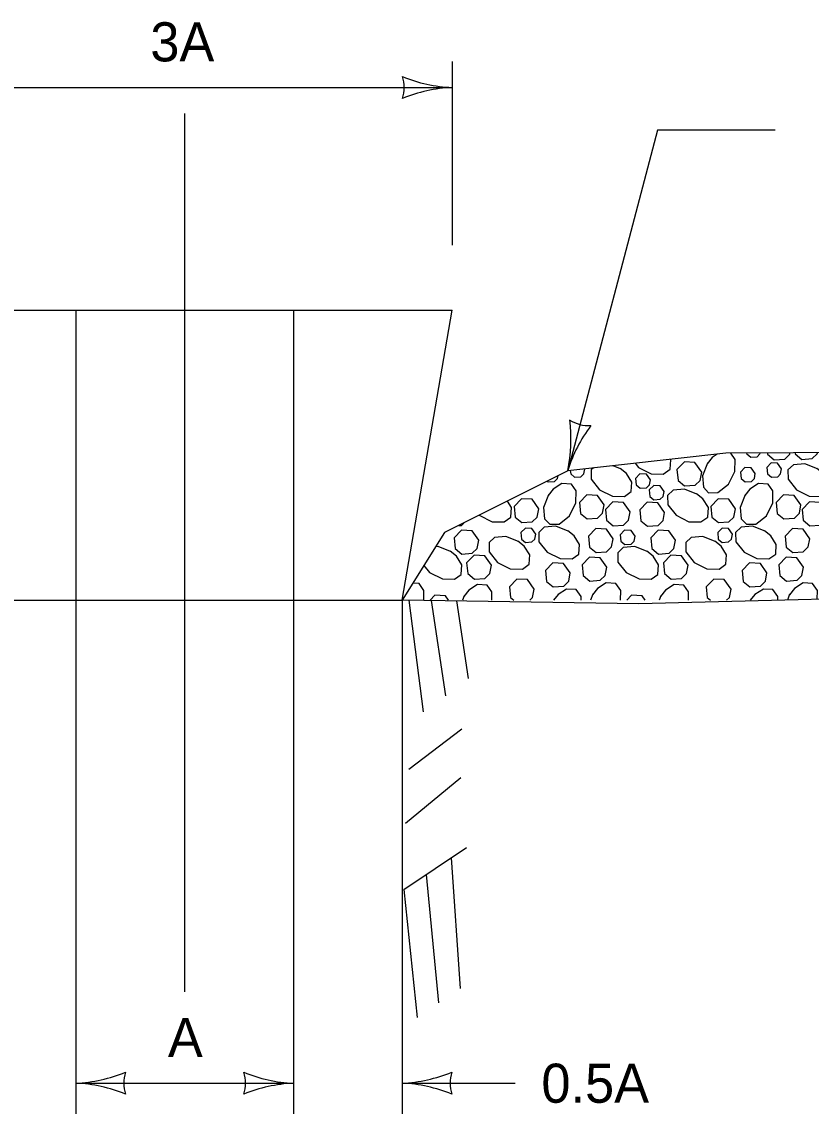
# Model space of a CAD drawing. Extents: x 49991.4 to 50021, y 49987.6 to 50011.4.
# Drawn here: x 50009.772 to 50010.982, y 49996.429 to 49998.093 of the extents above; entities that cross this region are included whole.
import ezdxf

# ---------------------------------------------------------------- set-up
doc = ezdxf.new("R2010")
doc.units = 0
for name, color, linetype in [('Level 1', 7, 'Continuous'), ('Level 2', 7, 'Continuous'), ('Level 3', 7, 'Continuous'), ('Level 6', 7, 'Continuous')]:
    doc.layers.add(name, color=color, linetype=linetype)

msp = doc.modelspace()

# ---------------------------------------------------------------- linework, layer by layer
at = {"layer": 'Level 1'}
for p, q in [((50009.6034, 49997.6503), (50010.4318, 49997.6503)), ((50009.6425, 49997.6503), (50010.4321, 49997.6503)), ((50009.8552, 49997.6503), (50009.8552, 49994.0392)), ((50010.1886, 49997.6503), (50010.1886, 49994.0392)), ((50010.3553, 49997.2058), (50010.4321, 49997.6503)), ((50010.6354, 49997.407), (50010.6353, 49997.4071)), ((50010.6901, 49997.4073), (50010.6785, 49997.4119)), ((50009.6885, 49997.2058), (50010.3553, 49997.2058)), ((50010.3553, 49997.2058), (50010.3553, 49994.0392)), ((50010.3653, 49997.2057), (50010.3872, 49997.0343)), ((50010.3996, 49997.2051), (50010.4218, 49997.0592)), ((50010.4385, 49997.2045), (50010.4566, 49997.0856)), ((50010.4503, 49997.2123), (50010.4477, 49997.2058)), ((50010.6477, 49997.2148), (50010.6441, 49997.2058)), ((50010.7518, 49997.2123), (50010.7492, 49997.2058)), ((50010.9492, 49997.2148), (50010.9457, 49997.2059)), ((50010.3655, 49996.9466), (50010.4466, 49997.0086)), ((50010.3603, 49996.8636), (50010.445, 49996.9338)), ((50010.3577, 49996.762), (50010.4541, 49996.8266)), ((50010.4305, 49996.8108), (50010.4444, 49996.6101)), ((50010.3918, 49996.7849), (50010.4107, 49996.588)), ((50010.3577, 49996.762), (50010.3781, 49996.5657))]:
    msp.add_line(p, q, dxfattribs=at)
for points in [[(50011.482, 49997.443), (50011.1627, 49997.4327), (50010.8516, 49997.431), (50010.609, 49997.4042), (50010.4204, 49997.3093), (50010.3553, 49997.2058)], [(50010.7123, 49997.4156), (50010.7174, 49997.4092), (50010.737, 49997.3993), (50010.7555, 49997.399), (50010.7659, 49997.4064), (50010.7669, 49997.4212), (50010.7666, 49997.4216)], [(50010.8144, 49997.4022), (50010.8041, 49997.4167), (50010.7878, 49997.4177), (50010.7764, 49997.4059), (50010.7781, 49997.3894), (50010.7882, 49997.381), (50010.8043, 49997.3821), (50010.8119, 49997.3895), (50010.8144, 49997.4022)], [(50010.8231, 49997.4157), (50010.8155, 49997.3965), (50010.817, 49997.3789), (50010.825, 49997.3705), (50010.8393, 49997.3708), (50010.8555, 49997.3835), (50010.8653, 49997.4031), (50010.8656, 49997.4216), (50010.8589, 49997.4311)], [(50010.8381, 49997.4295), (50010.8303, 49997.4246), (50010.8226, 49997.4149)], [(50010.8833, 49997.4312), (50010.8834, 49997.4301), (50010.8895, 49997.425), (50010.8992, 49997.4258), (50010.9037, 49997.4302), (50010.9039, 49997.4313)], [(50010.9153, 49997.4314), (50010.9155, 49997.4295), (50010.9256, 49997.4211), (50010.9417, 49997.4222), (50010.9493, 49997.4296), (50010.9497, 49997.4315)], [(50010.9575, 49997.4316), (50010.9576, 49997.4301), (50010.9677, 49997.4217), (50010.9839, 49997.4229), (50010.9915, 49997.4302), (50010.9918, 49997.4318)], [(50010.613, 49997.4047), (50010.6136, 49997.3993), (50010.6196, 49997.3943), (50010.6293, 49997.395), (50010.6339, 49997.3994), (50010.6354, 49997.407)], [(50010.6483, 49997.4086), (50010.645, 49997.4054), (50010.6452, 49997.3912), (50010.6579, 49997.3749), (50010.6776, 49997.3651), (50010.696, 49997.3648), (50010.7065, 49997.3722), (50010.7074, 49997.3869), (50010.699, 49997.4001), (50010.6893, 49997.4078)], [(50010.8966, 49997.3998), (50010.8904, 49997.4086), (50010.8806, 49997.4091), (50010.8738, 49997.402), (50010.8748, 49997.3921), (50010.8808, 49997.3871), (50010.8905, 49997.3878), (50010.8951, 49997.3922), (50010.8966, 49997.3998)], [(50010.9369, 49997.407), (50010.9308, 49997.4158), (50010.921, 49997.4163), (50010.9141, 49997.4093), (50010.9151, 49997.3993), (50010.9212, 49997.3943), (50010.9309, 49997.395), (50010.9354, 49997.3994), (50010.9369, 49997.407)], [(50010.9917, 49997.4073), (50010.9725, 49997.4149), (50010.9549, 49997.4134), (50010.9465, 49997.4054), (50010.9468, 49997.3912), (50010.9595, 49997.3749), (50010.9791, 49997.3651), (50010.9976, 49997.3648), (50011.008, 49997.3722), (50011.009, 49997.3869), (50011.0006, 49997.4001), (50010.9909, 49997.4078)], [(50010.5795, 49997.3673), (50010.5719, 49997.3481), (50010.5734, 49997.3305), (50010.5814, 49997.3222), (50010.5957, 49997.3224), (50010.6119, 49997.3351), (50010.6217, 49997.3548), (50010.6221, 49997.3733), (50010.6147, 49997.3837), (50010.5999, 49997.3847), (50010.5867, 49997.3762), (50010.579, 49997.3665)], [(50010.5776, 49997.3884), (50010.5793, 49997.3871), (50010.589, 49997.3878), (50010.5935, 49997.3922), (50010.5944, 49997.3969)], [(50010.7358, 49997.3902), (50010.7296, 49997.399), (50010.7198, 49997.3995), (50010.713, 49997.3924), (50010.714, 49997.3825), (50010.72, 49997.3775), (50010.7297, 49997.3782), (50010.7343, 49997.3826), (50010.7358, 49997.3902)], [(50010.8811, 49997.3673), (50010.8735, 49997.3481), (50010.875, 49997.3305), (50010.8829, 49997.3222), (50010.8972, 49997.3224), (50010.9135, 49997.3351), (50010.9233, 49997.3548), (50010.9236, 49997.3733), (50010.9162, 49997.3837), (50010.9015, 49997.3847), (50010.8883, 49997.3762), (50010.8806, 49997.3665)], [(50010.7569, 49997.3724), (50010.7508, 49997.3812), (50010.7409, 49997.3817), (50010.7341, 49997.3747), (50010.7351, 49997.3648), (50010.7412, 49997.3597), (50010.7509, 49997.3604), (50010.7554, 49997.3648), (50010.7569, 49997.3724)], [(50010.8072, 49997.3683), (50010.7881, 49997.3759), (50010.7705, 49997.3744), (50010.7621, 49997.3664), (50010.7624, 49997.3521), (50010.7751, 49997.3359), (50010.7947, 49997.3261), (50010.8132, 49997.3257), (50010.8236, 49997.3331), (50010.8246, 49997.3479), (50010.8161, 49997.361), (50010.8065, 49997.3688)], [(50010.4734, 49997.336), (50010.4735, 49997.3359), (50010.4931, 49997.3261), (50010.5116, 49997.3257), (50010.522, 49997.3331), (50010.523, 49997.3479), (50010.5167, 49997.3577)], [(50010.5648, 49997.3458), (50010.5545, 49997.3604), (50010.5382, 49997.3613), (50010.5268, 49997.3495), (50010.5284, 49997.333), (50010.5385, 49997.3246), (50010.5547, 49997.3258), (50010.5623, 49997.3331), (50010.5647, 49997.3458)], [(50010.665, 49997.3517), (50010.6548, 49997.3663), (50010.6384, 49997.3672), (50010.627, 49997.3554), (50010.6287, 49997.3389), (50010.6388, 49997.3305), (50010.6549, 49997.3317), (50010.6625, 49997.339), (50010.665, 49997.3517)], [(50010.7047, 49997.341), (50010.6945, 49997.3556), (50010.6781, 49997.3565), (50010.6668, 49997.3447), (50010.6684, 49997.3282), (50010.6785, 49997.3198), (50010.6947, 49997.321), (50010.7023, 49997.3283), (50010.7047, 49997.341)], [(50010.7576, 49997.3404), (50010.7473, 49997.355), (50010.731, 49997.3559), (50010.7196, 49997.3441), (50010.7213, 49997.3276), (50010.7314, 49997.3192), (50010.7475, 49997.3204), (50010.7551, 49997.3277), (50010.7576, 49997.3404)], [(50010.8663, 49997.3458), (50010.8561, 49997.3604), (50010.8397, 49997.3613), (50010.8283, 49997.3495), (50010.83, 49997.333), (50010.8401, 49997.3246), (50010.8562, 49997.3258), (50010.8638, 49997.3331), (50010.8663, 49997.3458)], [(50010.9665, 49997.3517), (50010.9563, 49997.3663), (50010.9399, 49997.3672), (50010.9286, 49997.3554), (50010.9302, 49997.3389), (50010.9403, 49997.3305), (50010.9565, 49997.3317), (50010.9641, 49997.339), (50010.9665, 49997.3517)], [(50011.0063, 49997.341), (50010.996, 49997.3556), (50010.9797, 49997.3565), (50010.9683, 49997.3447), (50010.97, 49997.3282), (50010.9801, 49997.3198), (50010.9962, 49997.321), (50011.0038, 49997.3283), (50011.0063, 49997.341)], [(50010.4419, 49997.3201), (50010.446, 49997.3204), (50010.4497, 49997.324)], [(50010.6099, 49997.3116), (50010.5907, 49997.3192), (50010.5731, 49997.3177), (50010.5648, 49997.3097), (50010.565, 49997.2954), (50010.5777, 49997.2792), (50010.5974, 49997.2694), (50010.6159, 49997.2691), (50010.6263, 49997.2765), (50010.6273, 49997.2912), (50010.6188, 49997.3044), (50010.6091, 49997.3121)], [(50010.9115, 49997.3116), (50010.8923, 49997.3192), (50010.8747, 49997.3177), (50010.8663, 49997.3097), (50010.8666, 49997.2954), (50010.8793, 49997.2792), (50010.8989, 49997.2694), (50010.9174, 49997.2691), (50010.9278, 49997.2765), (50010.9288, 49997.2912), (50010.9204, 49997.3044), (50010.9107, 49997.3121)], [(50010.4728, 49997.2977), (50010.4626, 49997.3123), (50010.4462, 49997.3132), (50010.4349, 49997.3014), (50010.4365, 49997.2849), (50010.4466, 49997.2765), (50010.4628, 49997.2777), (50010.4704, 49997.2851), (50010.4728, 49997.2977)], [(50010.5335, 49997.2959), (50010.5144, 49997.3035), (50010.4968, 49997.3019), (50010.4884, 49997.294), (50010.4887, 49997.2797), (50010.5014, 49997.2635), (50010.521, 49997.2536), (50010.5395, 49997.2533), (50010.5499, 49997.2607), (50010.5509, 49997.2755), (50010.5424, 49997.2886), (50010.5328, 49997.2964)], [(50010.5601, 49997.3071), (50010.5539, 49997.3158), (50010.5441, 49997.3164), (50010.5373, 49997.3093), (50010.5383, 49997.2994), (50010.5444, 49997.2944), (50010.554, 49997.2951), (50010.5586, 49997.2995), (50010.5601, 49997.3071)], [(50010.6786, 49997.2999), (50010.6684, 49997.3145), (50010.652, 49997.3155), (50010.6407, 49997.3037), (50010.6423, 49997.2871), (50010.6524, 49997.2787), (50010.6686, 49997.2799), (50010.6762, 49997.2873), (50010.6786, 49997.2999)], [(50010.7122, 49997.3037), (50010.7061, 49997.3125), (50010.6963, 49997.313), (50010.6894, 49997.3059), (50010.6904, 49997.296), (50010.6965, 49997.291), (50010.7062, 49997.2917), (50010.7107, 49997.2961), (50010.7122, 49997.3037)], [(50010.7744, 49997.2977), (50010.7641, 49997.3123), (50010.7478, 49997.3132), (50010.7364, 49997.3014), (50010.7381, 49997.2849), (50010.7482, 49997.2765), (50010.7643, 49997.2777), (50010.7719, 49997.2851), (50010.7744, 49997.2977)], [(50010.8351, 49997.2959), (50010.8159, 49997.3035), (50010.7983, 49997.3019), (50010.79, 49997.294), (50010.7902, 49997.2797), (50010.8029, 49997.2635), (50010.8225, 49997.2536), (50010.841, 49997.2533), (50010.8515, 49997.2607), (50010.8524, 49997.2755), (50010.844, 49997.2886), (50010.8343, 49997.2964)], [(50010.8616, 49997.3071), (50010.8555, 49997.3158), (50010.8457, 49997.3164), (50010.8389, 49997.3093), (50010.8398, 49997.2994), (50010.8459, 49997.2944), (50010.8556, 49997.2951), (50010.8602, 49997.2995), (50010.8616, 49997.3071)], [(50010.9802, 49997.2999), (50010.97, 49997.3145), (50010.9536, 49997.3155), (50010.9422, 49997.3037), (50010.9439, 49997.2871), (50010.954, 49997.2787), (50010.9701, 49997.2799), (50010.9777, 49997.2873), (50010.9802, 49997.2999)], [(50010.4294, 49997.2804), (50010.4103, 49997.288), (50010.4068, 49997.2877)], [(50010.731, 49997.2804), (50010.7118, 49997.288), (50010.6942, 49997.2864), (50010.6858, 49997.2785), (50010.6861, 49997.2642), (50010.6988, 49997.248), (50010.7184, 49997.2382), (50010.7369, 49997.2378), (50010.7473, 49997.2452), (50010.7483, 49997.26), (50010.7399, 49997.2731), (50010.7302, 49997.2809)], [(50010.3887, 49997.2589), (50010.3972, 49997.248), (50010.4169, 49997.2382), (50010.4354, 49997.2378), (50010.4458, 49997.2452), (50010.4468, 49997.26), (50010.4383, 49997.2731), (50010.4286, 49997.2809)], [(50010.4921, 49997.2592), (50010.4819, 49997.2737), (50010.4655, 49997.2747), (50010.4541, 49997.2629), (50010.4558, 49997.2464), (50010.4659, 49997.238), (50010.482, 49997.2391), (50010.4896, 49997.2465), (50010.4921, 49997.2592)], [(50010.669, 49997.2563), (50010.6588, 49997.2709), (50010.6424, 49997.2718), (50010.631, 49997.26), (50010.6327, 49997.2435), (50010.6428, 49997.2351), (50010.6589, 49997.2363), (50010.6665, 49997.2436), (50010.669, 49997.2563)], [(50010.7937, 49997.2592), (50010.7834, 49997.2737), (50010.7671, 49997.2747), (50010.7557, 49997.2629), (50010.7573, 49997.2464), (50010.7674, 49997.238), (50010.7836, 49997.2391), (50010.7912, 49997.2465), (50010.7937, 49997.2592)], [(50010.9706, 49997.2563), (50010.9603, 49997.2709), (50010.944, 49997.2718), (50010.9326, 49997.26), (50010.9342, 49997.2435), (50010.9443, 49997.2351), (50010.9605, 49997.2363), (50010.9681, 49997.2436), (50010.9706, 49997.2563)], [(50010.613, 49997.2474), (50010.6028, 49997.262), (50010.5864, 49997.2629), (50010.575, 49997.2511), (50010.5767, 49997.2346), (50010.5868, 49997.2262), (50010.6029, 49997.2273), (50010.6105, 49997.2347), (50010.613, 49997.2474)], [(50010.9145, 49997.2474), (50010.9043, 49997.262), (50010.8879, 49997.2629), (50010.8766, 49997.2511), (50010.8782, 49997.2346), (50010.8883, 49997.2262), (50010.9045, 49997.2273), (50010.9121, 49997.2347), (50010.9145, 49997.2474)], [(50010.5578, 49997.2226), (50010.5476, 49997.2372), (50010.5312, 49997.2381), (50010.5198, 49997.2263), (50010.5215, 49997.2098), (50010.5263, 49997.2058)], [(50010.8594, 49997.2226), (50010.8491, 49997.2372), (50010.8328, 49997.2381), (50010.8214, 49997.2263), (50010.823, 49997.2098), (50010.8278, 49997.2058)], [(50010.3884, 49997.2053), (50010.3887, 49997.2207), (50010.3813, 49997.2312), (50010.3716, 49997.2318)], [(50010.4926, 49997.2058), (50010.4928, 49997.2183), (50010.4854, 49997.2287), (50010.4707, 49997.2297), (50010.4575, 49997.2212), (50010.4498, 49997.2115)], [(50010.5511, 49997.2058), (50010.5553, 49997.2099), (50010.5578, 49997.2226)], [(50010.6294, 49997.2058), (50010.6295, 49997.2114), (50010.6221, 49997.2219), (50010.6074, 49997.2228), (50010.5942, 49997.2144), (50010.5873, 49997.2058)], [(50010.69, 49997.2058), (50010.6902, 49997.2207), (50010.6828, 49997.2312), (50010.6681, 49997.2321), (50010.6549, 49997.2237), (50010.6472, 49997.214)], [(50010.7941, 49997.2058), (50010.7944, 49997.2183), (50010.787, 49997.2287), (50010.7722, 49997.2297), (50010.759, 49997.2212), (50010.7513, 49997.2115)], [(50010.8526, 49997.2058), (50010.8569, 49997.2099), (50010.8594, 49997.2226)], [(50010.9309, 49997.2058), (50010.931, 49997.2114), (50010.9236, 49997.2219), (50010.9089, 49997.2228), (50010.8957, 49997.2144), (50010.8889, 49997.2058)], [(50010.9915, 49997.2071), (50010.9918, 49997.2207), (50010.9844, 49997.2312), (50010.9697, 49997.2321), (50010.9565, 49997.2237), (50010.9488, 49997.214)], [(50011.4448, 49997.2058), (50011.2866, 49997.2008), (50011.2358, 49997.2058), (50011.1066, 49997.2058), (50011.0231, 49997.2079), (50010.9416, 49997.2058), (50010.7182, 49997.2), (50010.3553, 49997.2058)], [(50010.4262, 49997.2058), (50010.4216, 49997.2124), (50010.4053, 49997.2133), (50010.398, 49997.2058)], [(50010.7278, 49997.2058), (50010.7232, 49997.2124), (50010.7068, 49997.2133), (50010.6996, 49997.2058)]]:
    msp.add_lwpolyline(points, dxfattribs=at)
at = {"layer": 'Level 3'}
for p, q in [((50010.4318, 49998.032), (50010.4318, 49997.7503)), ((50009.6034, 49997.992), (50010.4318, 49997.992)), ((50009.8552, 49996.4649), (50010.1886, 49996.4649)), ((50010.3553, 49996.4649), (50010.5287, 49996.4649))]:
    msp.add_line(p, q, dxfattribs=at)
msp.add_lwpolyline([(50010.9272, 49997.9266), (50010.7465, 49997.9266), (50010.609, 49997.4042)], dxfattribs=at)
for centre, radius, start, end in [((50010.441, 49998.2141), 0.2223, 247.456, 267.6395), ((50010.3036, 49997.992), 0.0548, 342.1388, 17.8612), ((50010.4433, 49997.7593), 0.233, 92.8273, 112.0772), ((50010.381, 49997.4524), 0.233, 348.0835, 7.3333), ((50010.381, 49997.4524), 0.233, 348.0835, 7.3333), ((50010.8215, 49997.3389), 0.2223, 142.7122, 162.8957), ((50010.8215, 49997.3389), 0.2223, 142.7122, 162.8957), ((50010.6416, 49997.5282), 0.0548, 237.395, 273.1173), ((50010.6416, 49997.5282), 0.0548, 237.395, 273.1173), ((50009.8437, 49996.6976), 0.233, 272.8273, 292.0772), ((50009.9834, 49996.4649), 0.0548, 162.1388, 197.8612), ((50010.1977, 49996.687), 0.2223, 247.456, 267.6395), ((50010.0603, 49996.4649), 0.0548, 342.1388, 17.8612), ((50010.3438, 49996.6976), 0.233, 272.8273, 292.0772), ((50010.4835, 49996.4649), 0.0548, 162.1388, 197.8612), ((50009.846, 49996.2428), 0.2223, 67.456, 87.6395), ((50010.2001, 49996.2322), 0.233, 92.8273, 112.0772), ((50010.3461, 49996.2428), 0.2223, 67.456, 87.6395)]:
    msp.add_arc(centre, radius, start, end, dxfattribs=at)
at = {"layer": 'Level 6'}
msp.add_line((50010.0219, 49996.6049), (50010.0219, 49997.952), dxfattribs=at)

# ---------------------------------------------------------------- texts
at = {"layer": 'Level 2'}
for s, p in [('3A', (50009.9692, 49998.032)), ('A', (50009.9961, 49996.5049)), ('0.5A', (50010.5687, 49996.4349))]:
    msp.add_text(s, height=0.06, dxfattribs=at).set_placement(p)

doc.saveas('drawing.dxf')
